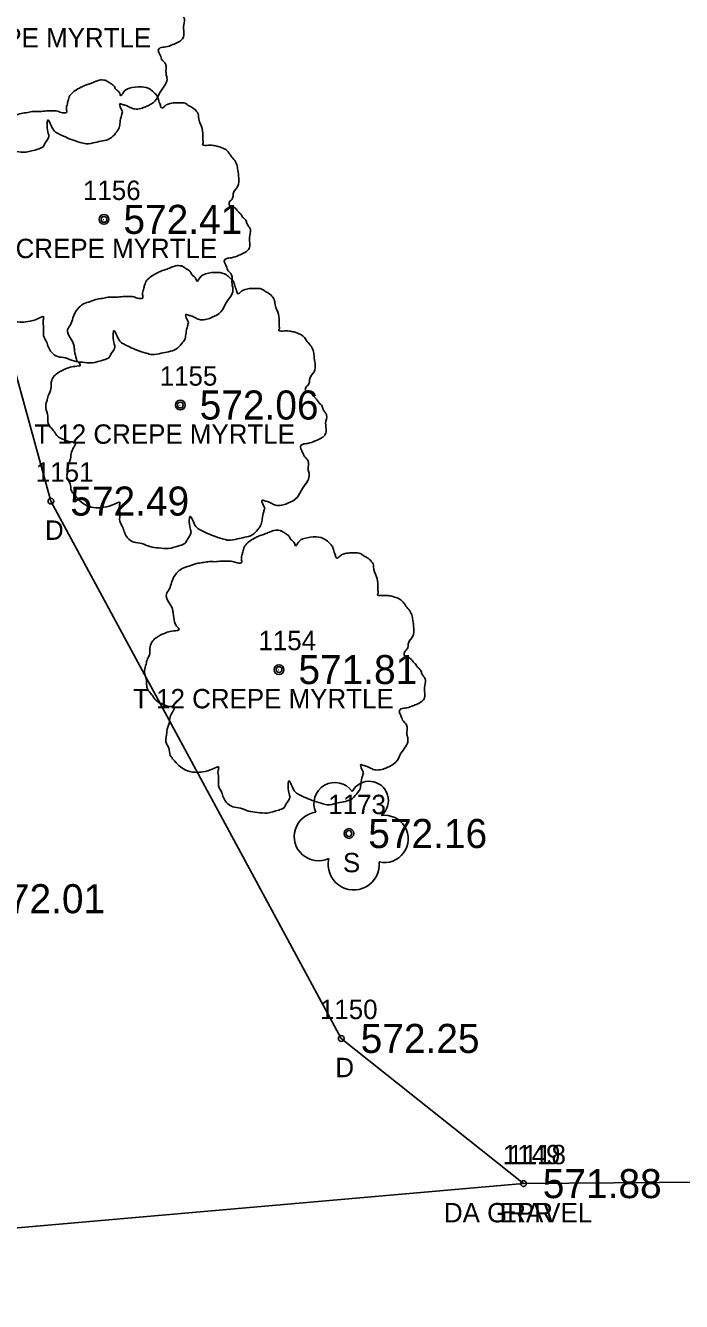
# Model space of a CAD drawing. Extents: x 1529475 to 1532053, y 876698 to 877911.
# Drawn here: x 1531055.4 to 1531089.3, y 877286.3 to 877352.1 of the extents above; entities that cross this region are included whole.
import ezdxf

# ---------------------------------------------------------------- set-up
doc = ezdxf.new("R2010")
doc.units = 0
for name, color, linetype in [('RD_EX_Driveway', 7, 'Continuous'), ('RD_EX_Driveway_txCode', 7, 'Continuous'), ('RD_EX_Road', 7, 'Continuous'), ('RD_EX_Road_txCode', 7, 'Continuous'), ('RD_EX_TX_Driveway_ELEV', 7, 'Continuous'), ('RD_EX_TX_Road_ELEV', 7, 'Continuous'), ('RD_EX_TX_VEG_ELEV', 7, 'Continuous'), ('RD_EX_VEG', 7, 'Continuous'), ('RD_EX_VEG_txCode', 7, 'Continuous'), ('RD_SMD_Locator', 7, 'Continuous')]:
    doc.layers.add(name, color=color, linetype=linetype)

msp = doc.modelspace()

# ---------------------------------------------------------------- linework, layer by layer
at = {"layer": 'RD_EX_Driveway'}
msp.add_lwpolyline([(1531081.114, 877292.384), (1531071.715, 877299.875), (1531056.729, 877327.604), (1531041.174, 877384.235)], dxfattribs=at)
at = {"layer": 'RD_EX_Road'}
msp.add_lwpolyline([(1531606.641, 877133.837), (1531579.15, 877155.048), (1531564.866, 877165.268), (1531535.216, 877186.029), (1531511.532, 877200.27), (1531474.57, 877218.901), (1531430.451, 877239.347), (1531404.48, 877249.379), (1531382.323, 877256.431), (1531333.233, 877270.709), (1531303.666, 877277.444), (1531276.518, 877282.709), (1531237.324, 877287.202), (1531185.802, 877290.94), (1531132.609, 877292.767), (1531081.114, 877292.384), (1531038.69, 877288.667), (1530976.423, 877285.451), (1530941.057, 877284.256)], dxfattribs=at)
at = {"layer": 'RD_EX_VEG'}
for centre, radius in [((1531059.47, 877342.141), 0.25), ((1531059.458, 877342.122), 0.0001), ((1531063.405, 877332.561), 0.25), ((1531063.392, 877332.542), 0.0001), ((1531068.501, 877318.909), 0.25), ((1531068.488, 877318.891), 0.0001), ((1531072.107, 877310.45), 0.25)]:
    msp.add_circle(centre, radius, dxfattribs=at)
for centre, radius, start, end in [((1531073.153, 877312.152), 0.995, 308.76261, 152.04674), ((1531071.386, 877311.997), 1.084, 34.97629, 204.75602), ((1531070.544, 877310.294), 1.257, 96.45179, 294.73401), ((1531073.947, 877310.171), 1.218, 256.56668, 98.10463), ((1531072.353, 877308.854), 1.318, 166.88266, 5.75893)]:
    msp.add_arc(centre, radius, start, end, dxfattribs=at)
for points in [[(1531056.197, 877360.182), (1531055.897, 877360.207), (1531055.572, 877360.107), (1531055.322, 877360.007), (1531055.097, 877359.932), (1531054.872, 877359.832), (1531054.572, 877359.658), (1531054.347, 877359.458), (1531054.222, 877359.208), (1531054.172, 877358.983), (1531054.123, 877358.708), (1531054.123, 877358.533), (1531053.998, 877358.508), (1531053.848, 877358.533), (1531053.598, 877358.608), (1531053.348, 877358.608), (1531053.098, 877358.608), (1531052.748, 877358.583), (1531052.398, 877358.583), (1531052.123, 877358.533), (1531051.799, 877358.483), (1531051.424, 877358.358), (1531051.074, 877358.233), (1531050.774, 877357.983), (1531050.524, 877357.509), (1531050.399, 877357.159), (1531050.249, 877356.909), (1531050.399, 877356.459), (1531050.574, 877356.109), (1531050.599, 877355.909), (1531050.674, 877355.484), (1531050.774, 877355.26), (1531050.899, 877355.06), (1531050.824, 877355.035), (1531050.449, 877354.985), (1531050.149, 877354.885), (1531049.724, 877354.66), (1531049.5, 877354.435), (1531049.4, 877354.11), (1531049.375, 877353.76), (1531049.275, 877353.56), (1531049.2, 877353.285), (1531049.175, 877353.21), (1531049.125, 877352.886), (1531049.225, 877352.436), (1531049.25, 877352.086), (1531049.375, 877351.861), (1531049.525, 877351.686), (1531049.699, 877351.436), (1531050.099, 877351.211), (1531050.424, 877351.111), (1531050.624, 877351.086), (1531050.449, 877350.587), (1531050.399, 877350.237), (1531050.274, 877349.837), (1531050.274, 877349.762), (1531050.224, 877349.287), (1531050.374, 877348.962), (1531050.449, 877348.587), (1531050.624, 877348.363), (1531050.899, 877348.063), (1531051.224, 877347.838), (1531051.724, 877347.713), (1531052.123, 877347.738), (1531052.698, 877347.913), (1531052.948, 877347.988), (1531052.923, 877347.813), (1531052.948, 877347.438), (1531052.948, 877347.013), (1531053.098, 877346.688), (1531053.198, 877346.413), (1531053.348, 877346.163), (1531053.673, 877345.939), (1531054.073, 877345.864), (1531054.497, 877345.714), (1531054.947, 877345.639), (1531055.447, 877345.614), (1531056.047, 877345.764), (1531056.322, 877345.889), (1531056.422, 877346.064), (1531056.621, 877346.438), (1531056.571, 877346.663), (1531056.596, 877347.263), (1531056.696, 877347.088), (1531056.871, 877346.738), (1531057.371, 877346.438), (1531057.771, 877346.263), (1531058.246, 877346.113), (1531058.546, 877346.039), (1531059.02, 877346.113), (1531059.395, 877346.188), (1531059.77, 877346.313), (1531060.07, 877346.588), (1531060.245, 877346.863), (1531060.295, 877347.138), (1531060.37, 877347.513), (1531060.42, 877347.688)], [(1531060.42, 877347.688), (1531060.345, 877347.863), (1531060.295, 877348.113), (1531060.37, 877348.088), (1531060.545, 877348.038), (1531060.82, 877347.913), (1531061.045, 877347.838), (1531061.369, 877347.863), (1531061.644, 877347.963), (1531062.094, 877348.238), (1531062.369, 877348.712), (1531062.644, 877349.112), (1531062.719, 877349.437), (1531062.669, 877349.662), (1531062.644, 877350.162), (1531062.444, 877350.412), (1531062.394, 877350.537), (1531062.294, 877350.936), (1531062.369, 877350.986), (1531062.644, 877351.036), (1531063.019, 877351.161), (1531063.294, 877351.286), (1531063.518, 877351.461), (1531063.593, 877351.686), (1531063.568, 877352.086), (1531063.618, 877352.486), (1531063.543, 877352.636), (1531063.443, 877352.786), (1531063.368, 877352.986), (1531063.219, 877353.135), (1531063.119, 877353.285), (1531063.019, 877353.385), (1531062.894, 877353.535), (1531062.719, 877353.66), (1531062.569, 877353.71), (1531062.519, 877353.86), (1531062.669, 877354.06), (1531062.719, 877354.16), (1531062.744, 877354.385), (1531062.969, 877354.735), (1531063.019, 877355.135), (1531062.969, 877355.559), (1531062.919, 877355.834), (1531062.769, 877356.109), (1531062.569, 877356.359), (1531062.444, 877356.534), (1531062.269, 877356.659), (1531061.944, 877356.784), (1531061.694, 877356.834), (1531061.344, 877356.834), (1531061.144, 877356.884), (1531061.169, 877356.934), (1531061.169, 877357.084), (1531061.169, 877357.359), (1531061.094, 877357.808), (1531060.945, 877358.308), (1531060.945, 877358.333), (1531060.845, 877358.583), (1531060.62, 877358.783), (1531060.445, 877358.883), (1531060.245, 877359.008), (1531059.995, 877359.033), (1531059.695, 877359.033), (1531059.42, 877358.983), (1531059.22, 877358.883), (1531059.045, 877358.758), (1531058.97, 877358.908), (1531058.87, 877359.208), (1531058.82, 877359.358), (1531058.671, 877359.533), (1531058.446, 877359.733), (1531057.996, 877359.857), (1531057.371, 877359.783), (1531057.071, 877359.583), (1531056.921, 877359.408), (1531056.871, 877359.533), (1531056.671, 877359.733), (1531056.571, 877359.907), (1531056.397, 877360.032), (1531056.247, 877360.132), (1531056.147, 877360.182)], [(1531059.602, 877349.308), (1531059.302, 877349.333), (1531058.977, 877349.233), (1531058.728, 877349.133), (1531058.503, 877349.058), (1531058.278, 877348.958), (1531057.978, 877348.783), (1531057.753, 877348.583), (1531057.628, 877348.333), (1531057.578, 877348.108), (1531057.528, 877347.834), (1531057.528, 877347.659), (1531057.403, 877347.634), (1531057.253, 877347.659), (1531057.003, 877347.734), (1531056.753, 877347.734), (1531056.503, 877347.734), (1531056.154, 877347.709), (1531055.804, 877347.709), (1531055.529, 877347.659), (1531055.204, 877347.609), (1531054.829, 877347.484), (1531054.479, 877347.359), (1531054.18, 877347.109), (1531053.93, 877346.634), (1531053.805, 877346.284), (1531053.655, 877346.034), (1531053.805, 877345.585), (1531053.98, 877345.235), (1531054.005, 877345.035), (1531054.08, 877344.61), (1531054.18, 877344.385), (1531054.304, 877344.185), (1531054.23, 877344.16), (1531053.855, 877344.11), (1531053.555, 877344.01), (1531053.13, 877343.785), (1531052.905, 877343.56), (1531052.805, 877343.236), (1531052.78, 877342.886), (1531052.68, 877342.686), (1531052.605, 877342.411), (1531052.58, 877342.336), (1531052.53, 877342.011), (1531052.63, 877341.561), (1531052.655, 877341.211), (1531052.78, 877340.987), (1531052.93, 877340.812), (1531053.105, 877340.562), (1531053.505, 877340.337), (1531053.83, 877340.237), (1531054.03, 877340.212), (1531053.855, 877339.712), (1531053.805, 877339.362), (1531053.68, 877338.962), (1531053.68, 877338.888), (1531053.63, 877338.413), (1531053.78, 877338.088), (1531053.855, 877337.713), (1531054.03, 877337.488), (1531054.304, 877337.188), (1531054.629, 877336.963), (1531055.129, 877336.838), (1531055.529, 877336.863), (1531056.104, 877337.038), (1531056.354, 877337.113), (1531056.329, 877336.938), (1531056.354, 877336.563), (1531056.354, 877336.139), (1531056.503, 877335.814), (1531056.603, 877335.539), (1531056.753, 877335.289), (1531057.078, 877335.064), (1531057.478, 877334.989), (1531057.903, 877334.839), (1531058.353, 877334.764), (1531058.852, 877334.739), (1531059.452, 877334.889), (1531059.727, 877335.014), (1531059.827, 877335.189), (1531060.027, 877335.564), (1531059.977, 877335.789), (1531060.002, 877336.389), (1531060.102, 877336.214), (1531060.277, 877335.864), (1531060.777, 877335.564), (1531061.176, 877335.389), (1531061.651, 877335.239), (1531061.951, 877335.164), (1531062.426, 877335.239), (1531062.801, 877335.314), (1531063.176, 877335.439), (1531063.475, 877335.714), (1531063.65, 877335.989), (1531063.7, 877336.264), (1531063.775, 877336.638), (1531063.825, 877336.813)], [(1531063.825, 877336.813), (1531063.75, 877336.988), (1531063.7, 877337.238), (1531063.775, 877337.213), (1531063.95, 877337.163), (1531064.225, 877337.038), (1531064.45, 877336.963), (1531064.775, 877336.988), (1531065.05, 877337.088), (1531065.5, 877337.363), (1531065.774, 877337.838), (1531066.049, 877338.238), (1531066.124, 877338.563), (1531066.074, 877338.788), (1531066.049, 877339.287), (1531065.849, 877339.537), (1531065.799, 877339.662), (1531065.699, 877340.062), (1531065.774, 877340.112), (1531066.049, 877340.162), (1531066.424, 877340.287), (1531066.699, 877340.412), (1531066.924, 877340.587), (1531066.999, 877340.812), (1531066.974, 877341.211), (1531067.024, 877341.611), (1531066.949, 877341.761), (1531066.849, 877341.911), (1531066.774, 877342.111), (1531066.624, 877342.261), (1531066.524, 877342.411), (1531066.424, 877342.511), (1531066.299, 877342.661), (1531066.124, 877342.786), (1531065.974, 877342.836), (1531065.924, 877342.986), (1531066.074, 877343.186), (1531066.124, 877343.286), (1531066.149, 877343.51), (1531066.374, 877343.86), (1531066.424, 877344.26), (1531066.374, 877344.685), (1531066.324, 877344.96), (1531066.174, 877345.235), (1531065.974, 877345.485), (1531065.849, 877345.66), (1531065.674, 877345.784), (1531065.35, 877345.909), (1531065.1, 877345.959), (1531064.75, 877345.959), (1531064.55, 877346.009), (1531064.575, 877346.059), (1531064.575, 877346.209), (1531064.575, 877346.484), (1531064.5, 877346.934), (1531064.35, 877347.434), (1531064.35, 877347.459), (1531064.25, 877347.709), (1531064.025, 877347.909), (1531063.85, 877348.008), (1531063.65, 877348.133), (1531063.4, 877348.158), (1531063.101, 877348.158), (1531062.826, 877348.108), (1531062.626, 877348.008), (1531062.451, 877347.884), (1531062.376, 877348.033), (1531062.276, 877348.333), (1531062.226, 877348.483), (1531062.076, 877348.658), (1531061.851, 877348.858), (1531061.401, 877348.983), (1531060.777, 877348.908), (1531060.477, 877348.708), (1531060.327, 877348.533), (1531060.277, 877348.658), (1531060.077, 877348.858), (1531059.977, 877349.033), (1531059.802, 877349.158), (1531059.652, 877349.258), (1531059.552, 877349.308)], [(1531063.536, 877339.728), (1531063.237, 877339.753), (1531062.912, 877339.653), (1531062.662, 877339.553), (1531062.437, 877339.478), (1531062.212, 877339.378), (1531061.912, 877339.203), (1531061.687, 877339.003), (1531061.562, 877338.753), (1531061.512, 877338.528), (1531061.462, 877338.253), (1531061.462, 877338.078), (1531061.337, 877338.053), (1531061.187, 877338.078), (1531060.938, 877338.153), (1531060.688, 877338.153), (1531060.438, 877338.153), (1531060.088, 877338.128), (1531059.738, 877338.128), (1531059.463, 877338.078), (1531059.138, 877338.029), (1531058.764, 877337.904), (1531058.414, 877337.779), (1531058.114, 877337.529), (1531057.864, 877337.054), (1531057.739, 877336.704), (1531057.589, 877336.454), (1531057.739, 877336.004), (1531057.914, 877335.655), (1531057.939, 877335.455), (1531058.014, 877335.03), (1531058.114, 877334.805), (1531058.239, 877334.605), (1531058.164, 877334.58), (1531057.789, 877334.53), (1531057.489, 877334.43), (1531057.064, 877334.205), (1531056.839, 877333.98), (1531056.739, 877333.655), (1531056.714, 877333.306), (1531056.615, 877333.106), (1531056.54, 877332.831), (1531056.515, 877332.756), (1531056.465, 877332.431), (1531056.565, 877331.981), (1531056.59, 877331.631), (1531056.714, 877331.406), (1531056.864, 877331.232), (1531057.039, 877330.982), (1531057.439, 877330.757), (1531057.764, 877330.657), (1531057.964, 877330.632), (1531057.789, 877330.132), (1531057.739, 877329.782), (1531057.614, 877329.382), (1531057.614, 877329.307), (1531057.564, 877328.833), (1531057.714, 877328.508), (1531057.789, 877328.133), (1531057.964, 877327.908), (1531058.239, 877327.608), (1531058.564, 877327.383), (1531059.063, 877327.258), (1531059.463, 877327.283), (1531060.038, 877327.458), (1531060.288, 877327.533), (1531060.263, 877327.358), (1531060.288, 877326.983), (1531060.288, 877326.559), (1531060.438, 877326.234), (1531060.538, 877325.959), (1531060.688, 877325.709), (1531061.013, 877325.484), (1531061.412, 877325.409), (1531061.837, 877325.259), (1531062.287, 877325.184), (1531062.787, 877325.159), (1531063.387, 877325.309), (1531063.661, 877325.434), (1531063.761, 877325.609), (1531063.961, 877325.984), (1531063.911, 877326.209), (1531063.936, 877326.808), (1531064.036, 877326.633), (1531064.211, 877326.284), (1531064.711, 877325.984), (1531065.111, 877325.809), (1531065.586, 877325.659), (1531065.885, 877325.584), (1531066.36, 877325.659), (1531066.735, 877325.734), (1531067.11, 877325.859), (1531067.41, 877326.134), (1531067.585, 877326.409), (1531067.635, 877326.683), (1531067.71, 877327.058), (1531067.76, 877327.233)], [(1531067.76, 877327.233), (1531067.685, 877327.408), (1531067.635, 877327.658), (1531067.71, 877327.633), (1531067.885, 877327.583), (1531068.159, 877327.458), (1531068.384, 877327.383), (1531068.709, 877327.408), (1531068.984, 877327.508), (1531069.434, 877327.783), (1531069.709, 877328.258), (1531069.984, 877328.658), (1531070.059, 877328.982), (1531070.009, 877329.207), (1531069.984, 877329.707), (1531069.784, 877329.957), (1531069.734, 877330.082), (1531069.634, 877330.482), (1531069.709, 877330.532), (1531069.984, 877330.582), (1531070.358, 877330.707), (1531070.633, 877330.832), (1531070.858, 877331.007), (1531070.933, 877331.232), (1531070.908, 877331.631), (1531070.958, 877332.031), (1531070.883, 877332.181), (1531070.783, 877332.331), (1531070.708, 877332.531), (1531070.558, 877332.681), (1531070.458, 877332.831), (1531070.358, 877332.931), (1531070.234, 877333.081), (1531070.059, 877333.206), (1531069.909, 877333.256), (1531069.859, 877333.406), (1531070.009, 877333.605), (1531070.059, 877333.705), (1531070.084, 877333.93), (1531070.309, 877334.28), (1531070.358, 877334.68), (1531070.309, 877335.105), (1531070.259, 877335.38), (1531070.109, 877335.655), (1531069.909, 877335.904), (1531069.784, 877336.079), (1531069.609, 877336.204), (1531069.284, 877336.329), (1531069.034, 877336.379), (1531068.684, 877336.379), (1531068.484, 877336.429), (1531068.509, 877336.479), (1531068.509, 877336.629), (1531068.509, 877336.904), (1531068.434, 877337.354), (1531068.284, 877337.854), (1531068.284, 877337.879), (1531068.184, 877338.128), (1531067.96, 877338.328), (1531067.785, 877338.428), (1531067.585, 877338.553), (1531067.335, 877338.578), (1531067.035, 877338.578), (1531066.76, 877338.528), (1531066.56, 877338.428), (1531066.385, 877338.303), (1531066.31, 877338.453), (1531066.21, 877338.753), (1531066.16, 877338.903), (1531066.01, 877339.078), (1531065.786, 877339.278), (1531065.336, 877339.403), (1531064.711, 877339.328), (1531064.411, 877339.128), (1531064.261, 877338.953), (1531064.211, 877339.078), (1531064.011, 877339.278), (1531063.911, 877339.453), (1531063.736, 877339.578), (1531063.586, 877339.678), (1531063.486, 877339.728)], [(1531068.633, 877326.077), (1531068.333, 877326.102), (1531068.008, 877326.002), (1531067.758, 877325.902), (1531067.533, 877325.827), (1531067.308, 877325.727), (1531067.009, 877325.552), (1531066.784, 877325.352), (1531066.659, 877325.102), (1531066.609, 877324.877), (1531066.559, 877324.602), (1531066.559, 877324.427), (1531066.434, 877324.402), (1531066.284, 877324.427), (1531066.034, 877324.502), (1531065.784, 877324.502), (1531065.534, 877324.502), (1531065.184, 877324.477), (1531064.834, 877324.477), (1531064.56, 877324.427), (1531064.235, 877324.377), (1531063.86, 877324.252), (1531063.51, 877324.127), (1531063.21, 877323.878), (1531062.96, 877323.403), (1531062.835, 877323.053), (1531062.685, 877322.803), (1531062.835, 877322.353), (1531063.01, 877322.003), (1531063.035, 877321.803), (1531063.11, 877321.379), (1531063.21, 877321.154), (1531063.335, 877320.954), (1531063.26, 877320.929), (1531062.885, 877320.879), (1531062.585, 877320.779), (1531062.161, 877320.554), (1531061.936, 877320.329), (1531061.836, 877320.004), (1531061.811, 877319.654), (1531061.711, 877319.455), (1531061.636, 877319.18), (1531061.611, 877319.105), (1531061.561, 877318.78), (1531061.661, 877318.33), (1531061.686, 877317.98), (1531061.811, 877317.755), (1531061.961, 877317.58), (1531062.136, 877317.33), (1531062.535, 877317.106), (1531062.86, 877317.006), (1531063.06, 877316.981), (1531062.885, 877316.481), (1531062.835, 877316.131), (1531062.71, 877315.731), (1531062.71, 877315.656), (1531062.66, 877315.181), (1531062.81, 877314.856), (1531062.885, 877314.482), (1531063.06, 877314.257), (1531063.335, 877313.957), (1531063.66, 877313.732), (1531064.16, 877313.607), (1531064.56, 877313.632), (1531065.134, 877313.807), (1531065.384, 877313.882), (1531065.359, 877313.707), (1531065.384, 877313.332), (1531065.384, 877312.907), (1531065.534, 877312.583), (1531065.634, 877312.308), (1531065.784, 877312.058), (1531066.109, 877311.833), (1531066.509, 877311.758), (1531066.934, 877311.608), (1531067.383, 877311.533), (1531067.883, 877311.508), (1531068.483, 877311.658), (1531068.758, 877311.783), (1531068.858, 877311.958), (1531069.058, 877312.333), (1531069.008, 877312.558), (1531069.033, 877313.157), (1531069.133, 877312.982), (1531069.308, 877312.632), (1531069.807, 877312.333), (1531070.207, 877312.158), (1531070.682, 877312.008), (1531070.982, 877311.933), (1531071.457, 877312.008), (1531071.831, 877312.083), (1531072.206, 877312.208), (1531072.506, 877312.483), (1531072.681, 877312.757), (1531072.731, 877313.032), (1531072.806, 877313.407), (1531072.856, 877313.582)], [(1531072.856, 877313.582), (1531072.781, 877313.757), (1531072.731, 877314.007), (1531072.806, 877313.982), (1531072.981, 877313.932), (1531073.256, 877313.807), (1531073.481, 877313.732), (1531073.806, 877313.757), (1531074.08, 877313.857), (1531074.53, 877314.132), (1531074.805, 877314.607), (1531075.08, 877315.006), (1531075.155, 877315.331), (1531075.105, 877315.556), (1531075.08, 877316.056), (1531074.88, 877316.306), (1531074.83, 877316.431), (1531074.73, 877316.831), (1531074.805, 877316.881), (1531075.08, 877316.931), (1531075.455, 877317.056), (1531075.73, 877317.18), (1531075.955, 877317.355), (1531076.03, 877317.58), (1531076.005, 877317.98), (1531076.055, 877318.38), (1531075.98, 877318.53), (1531075.88, 877318.68), (1531075.805, 877318.88), (1531075.655, 877319.03), (1531075.555, 877319.18), (1531075.455, 877319.28), (1531075.33, 877319.43), (1531075.155, 877319.554), (1531075.005, 877319.604), (1531074.955, 877319.754), (1531075.105, 877319.954), (1531075.155, 877320.054), (1531075.18, 877320.279), (1531075.405, 877320.629), (1531075.455, 877321.029), (1531075.405, 877321.454), (1531075.355, 877321.729), (1531075.205, 877322.003), (1531075.005, 877322.253), (1531074.88, 877322.428), (1531074.705, 877322.553), (1531074.38, 877322.678), (1531074.13, 877322.728), (1531073.781, 877322.728), (1531073.581, 877322.778), (1531073.606, 877322.828), (1531073.606, 877322.978), (1531073.606, 877323.253), (1531073.531, 877323.703), (1531073.381, 877324.202), (1531073.381, 877324.227), (1531073.281, 877324.477), (1531073.056, 877324.677), (1531072.881, 877324.777), (1531072.681, 877324.902), (1531072.431, 877324.927), (1531072.131, 877324.927), (1531071.856, 877324.877), (1531071.656, 877324.777), (1531071.482, 877324.652), (1531071.407, 877324.802), (1531071.307, 877325.102), (1531071.257, 877325.252), (1531071.107, 877325.427), (1531070.882, 877325.627), (1531070.432, 877325.752), (1531069.807, 877325.677), (1531069.507, 877325.477), (1531069.357, 877325.302), (1531069.308, 877325.427), (1531069.108, 877325.627), (1531069.008, 877325.802), (1531068.833, 877325.927), (1531068.683, 877326.027), (1531068.583, 877326.077)]]:
    msp.add_spline(points, degree=3, dxfattribs=at)
at = {"layer": 'RD_SMD_Locator'}
for centre in [(1531059.47, 877342.141), (1531063.405, 877332.561), (1531056.729, 877327.604), (1531068.501, 877318.909), (1531072.107, 877310.45), (1531071.715, 877299.875), (1531081.114, 877292.384), (1531081.114, 877292.384)]:
    msp.add_circle(centre, 0.15, dxfattribs=at)

# ---------------------------------------------------------------- texts
at = {"layer": 'RD_EX_Driveway_txCode'}
for s, p in [('1151', (1531055.95, 877328.604)), ('D', (1531056.422, 877325.604)), ('1150', (1531070.612, 877300.875)), ('D', (1531071.408, 877297.875)), ('1149', (1531080.051, 877293.384)), ('DA GRAVEL', (1531077.012, 877290.384))]:
    msp.add_text(s, height=1, dxfattribs=at).set_placement(p)
at = {"layer": 'RD_EX_Road_txCode'}
for s, p in [('1118', (1531080.335, 877293.384)), ('EPR', (1531079.886, 877290.384))]:
    msp.add_text(s, height=1, dxfattribs=at).set_placement(p)
at = {"layer": 'RD_EX_TX_Driveway_ELEV'}
for s, p in [('572.49', (1531057.729, 877326.854)), ('572.01', (1531053.392, 877306.335)), ('572.25', (1531072.715, 877299.125)), ('571.88', (1531082.114, 877291.634))]:
    msp.add_text(s, height=1.5, dxfattribs=at).set_placement(p)
at = {"layer": 'RD_EX_TX_Road_ELEV'}
msp.add_text('571.88', height=1.5, dxfattribs=at).set_placement((1531082.114, 877291.634))
at = {"layer": 'RD_EX_TX_VEG_ELEV'}
for s, p in [('572.41', (1531060.47, 877341.391)), ('572.06', (1531064.405, 877331.811)), ('571.81', (1531069.501, 877318.159)), ('572.16', (1531073.107, 877309.7))]:
    msp.add_text(s, height=1.5, dxfattribs=at).set_placement(p)
at = {"layer": 'RD_EX_VEG_txCode'}
for s, p in [('T 10 CREPE MYRTLE', (1531048.454, 877351.015)), ('1156', (1531058.384, 877343.141)), ('T 10 CREPE MYRTLE', (1531051.86, 877340.141)), ('1155', (1531062.342, 877333.561)), ('T 12 CREPE MYRTLE', (1531055.873, 877330.561)), ('1154', (1531067.438, 877319.909)), ('T 12 CREPE MYRTLE', (1531060.969, 877316.909)), ('1173', (1531071.044, 877311.45)), ('S', (1531071.8, 877308.45))]:
    msp.add_text(s, height=1, dxfattribs=at).set_placement(p)

doc.saveas('drawing.dxf')
